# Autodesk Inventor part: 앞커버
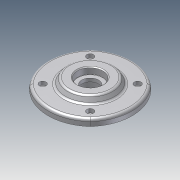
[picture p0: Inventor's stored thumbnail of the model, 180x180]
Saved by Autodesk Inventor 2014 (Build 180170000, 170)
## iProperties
Company: 한국ATC센터
Created: 2014-08
Part Number: 앞커버
Document SubType Name: Modeling
Designer: KYOUNG IL JANG
Density: 1 g/cm^3
Material: 일반
Appearance: 기본값
Mass: 89.0213 g
Surface Area: 231.958 cm^2
Volume: 89.0213 cm^3
Author: KYOUNG IL JANG
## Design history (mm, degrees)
sketch "스케치1"
  geometry: C1 r 30 at (0, 0) reference; A1 r 53.623 centre (0, -3.623) between (36.062, 36.062) and (-36.062, 36.062) reference; A2 r 53.623 centre (3.623, 0) between (-36.062, 36.062) and (-36.062, -36.062) reference; A3 r 53.623 centre (-3.623, 0) between (36.062, -36.062) and (36.062, 36.062) reference; A4 r 53.623 centre (0, 3.623) between (-36.062, -36.062) and (36.062, -36.062) reference; 1 further point
  node "참조9"
  node "참조14"
  node "참조15"
  node "참조16"
  node "참조17"
extrude "돌출1" new body sketch "스케치1" distance "d0" = 8; taper "d1" = 0 deg
sketch "스케치2"
  geometry: C1 r 30 at (0, 0); 1 further point
  constraints: 1 centre point, 1 coincident
  dimensions: "d2" = 60 diameter of C1
extrude "돌출2" join sketch "스케치2" distance "d3" = 7; taper "d4" = -30 deg
hole "구멍1" diameter "d7" = 20; stored, may be unused: countersink angle "d11" = 90 deg, drill point angle "d13" = 118 deg; dims "d5" = 10, "d6" = 10, "d8" = 6, "d9" = 30, "d10" = 8, "d12" = 20
sketch "스케치3"
  geometry: C1 r 1.621 at (28.284, 28.284) reference; C2 r 1.621 at (-28.284, 28.284) reference; C3 r 1.621 at (-28.284, -28.284) reference; C4 r 1.621 at (28.284, -28.284) reference; 1 further point
hole "구멍2" sketch "스케치3" at (28.284, 28.284), (28.284, -28.284), (-28.284, -28.284), (-28.284, 28.284) diameter "d14" = 4.5; stored, may be unused: countersink angle "d18" = 90 deg, drill point angle "d20" = 118 deg; dims "d15" = 6, "d16" = 8, "d17" = 4.4, "d19" = 20
extrude "돌출3" join sketch "스케치1" distance "d21" = 12; taper "d22" = 0 deg
hole "구멍3" diameter "d25" = 30; stored, may be unused: countersink angle "d29" = 90 deg, drill point angle "d31" = 0 deg; dims "d23" = 10, "d24" = 10, "d26" = 6, "d27" = 40, "d28" = 12, "d30" = 15
fillet "모깎기1" dims "d32" = 3, "d33" = 0.3
chamfer "모따기1" distance "d34" = 1; stored, may be unused: second distance "d35" = 2, angle "d36" = 45 deg
node "솔리드1"
node "참조10"
node "참조11"
node "참조12"
node "참조13"
